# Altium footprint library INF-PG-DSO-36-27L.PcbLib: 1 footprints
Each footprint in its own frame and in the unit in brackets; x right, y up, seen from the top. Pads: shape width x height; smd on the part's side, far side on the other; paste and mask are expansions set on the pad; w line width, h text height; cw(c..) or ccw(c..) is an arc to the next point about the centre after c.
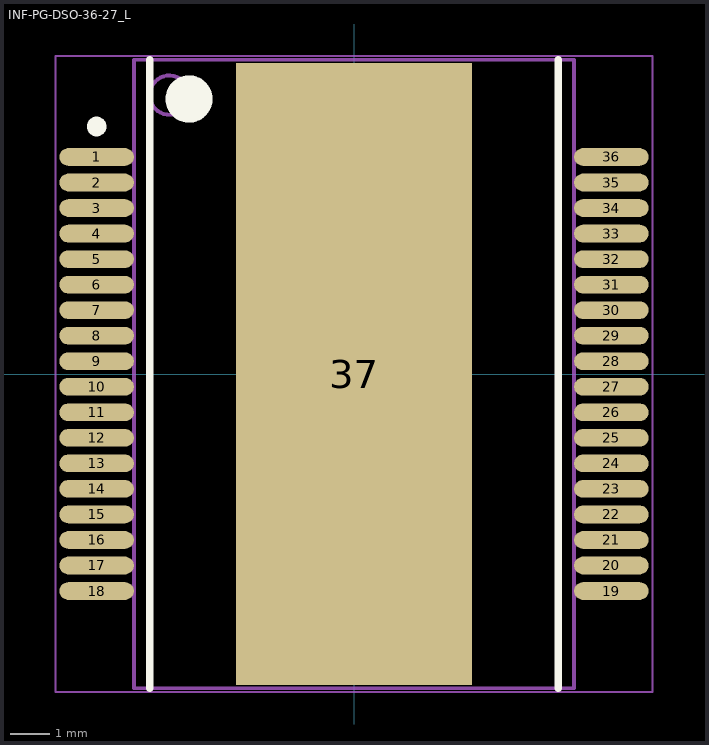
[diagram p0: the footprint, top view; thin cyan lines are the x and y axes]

## INF-PG-DSO-36-27_L [mm] "SOP, 36-Leads, Body 15.9x11mm, Pitch 0.65mm, Thermal Pad 15.84x6mm, IPC High Density"
height 3.5
pads (37):
  oval 1.9x0.45 smd: 1(-6.55,5.525) 2(-6.55,4.875) 3(-6.55,4.225) 4(-6.55,3.575) 5(-6.55,2.925) 6(-6.55,2.275) 7(-6.55,1.625) 8(-6.55,0.975) 9(-6.55,0.325) 10(-6.55,-0.325) 11(-6.55,-0.975) 12(-6.55,-1.625) 13(-6.55,-2.275) 14(-6.55,-2.925) 15(-6.55,-3.575) 16(-6.55,-4.225) 17(-6.55,-4.875) 18(-6.55,-5.525) 19(6.55,-5.525) 20(6.55,-4.875) 21(6.55,-4.225) 22(6.55,-3.575) 23(6.55,-2.925) 24(6.55,-2.275) 25(6.55,-1.625) 26(6.55,-0.975) 27(6.55,-0.325) 28(6.55,0.325) 29(6.55,0.975) 30(6.55,1.625) 31(6.55,2.275) 32(6.55,2.925) 33(6.55,3.575) 34(6.55,4.225) 35(6.55,4.875) 36(6.55,5.525)
  rect 6x15.84 smd: 37(0,0)
Top Overlay:
  circle w0.6: c-4.2,7 r0.3
  circle w0.25: c-6.55,6.3 r0.125
  lines w0.2: -5.2,-8 -5.2,8 ; 5.2,-8 5.2,8
Mechanical 13:
  circle w0.1: c-4.7,7.1 r0.5
  lines w0.1: -5.6,-8 5.6,-8 5.6,8 -5.6,8 -5.6,-8
Mechanical 15:
  lines w0.05: -7.6,-8.1 7.6,-8.1 7.6,8.1 -7.6,8.1 -7.6,-8.1
  lines w0.1: -0.5,0 0.5,0 ; 0,-0.5 0,0.5
3D body: height 3.5, standoff 0, extent -5.6,-8 5.6,8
